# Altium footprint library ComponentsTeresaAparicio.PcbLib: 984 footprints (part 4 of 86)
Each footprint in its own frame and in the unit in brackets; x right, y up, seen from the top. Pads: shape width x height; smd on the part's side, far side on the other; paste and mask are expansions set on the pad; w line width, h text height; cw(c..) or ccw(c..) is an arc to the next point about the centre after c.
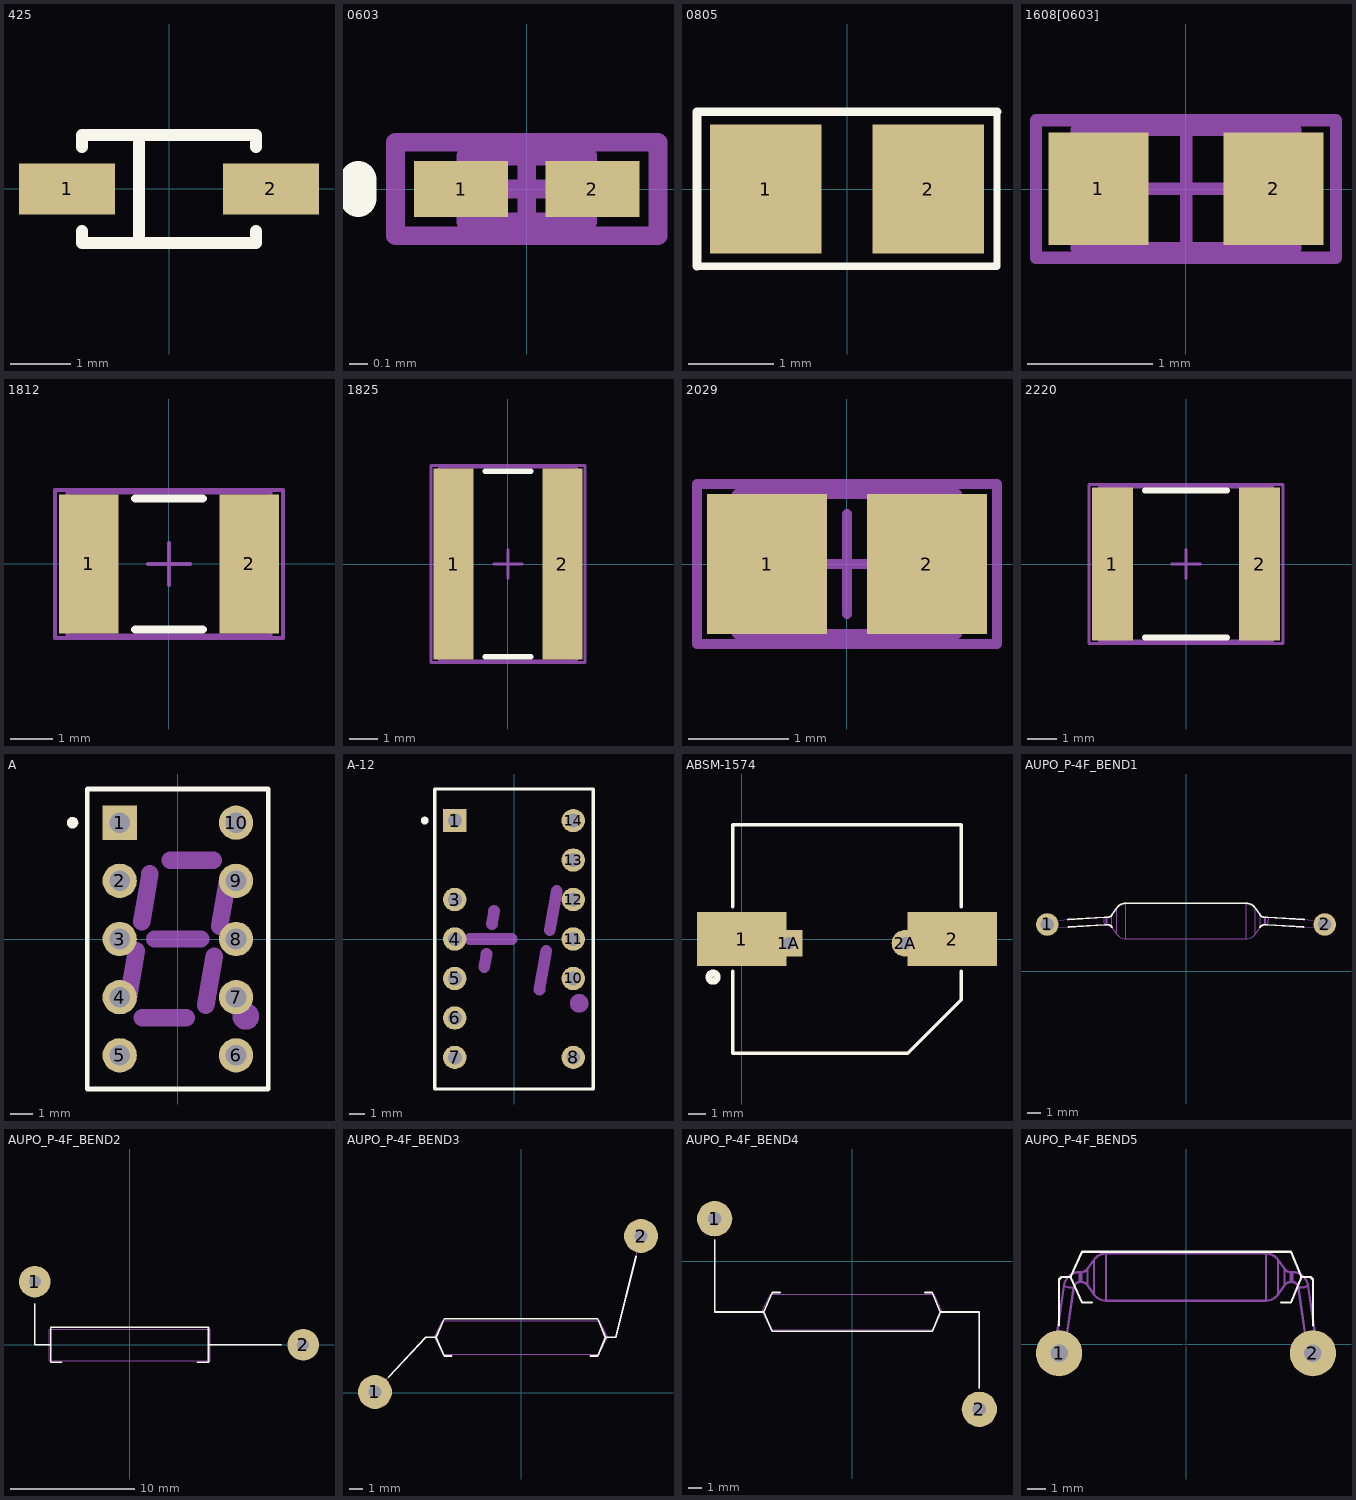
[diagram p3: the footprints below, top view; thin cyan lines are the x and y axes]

## 425 [mm] "SOD-123; 2 Leads; Body 2.7 x 1.6 mm, (LxW)"
height 1.35
pads (2):
  rect 1.6x0.85 smd: 1(-1.7,0) 2(1.7,0)
Top Overlay:
  lines w0.2: -1.45,-0.7 -1.45,-0.9 1.45,-0.9 1.45,-0.7 ; -1.45,0.7 -1.45,0.9 1.45,0.9 1.45,0.7 ; -0.5,-0.9 -0.5,0.9

## 0603 [mm] "Chip Inductor, Body 0.6x0.3mm, IPC High Density"
height 0.55
pads (2):
  rect 0.5x0.3 smd: 1(-0.35,0) 2(0.35,0)
Top Overlay:
  lines w0.2: -0.9,-0.05 -0.9,0.05
Mechanical 13:
  lines w0.1: -0.325,-0.175 0.325,-0.175 0.325,0.175 -0.325,0.175 -0.325,-0.175
Mechanical 15:
  lines w0.1: -0.175,0 0.175,0 ; 0,-0.175 0,0.175 ; -0.7,-0.25 0.7,-0.25 0.7,0.25 -0.7,0.25 -0.7,-0.25
3D body: height 0.55, standoff 0, extent -0.325,-0.175 0.325,0.175

## 0805 [mm] "Chip Capacitor; Body 2.0 x 1.2 mm (LxW typ)"
height 1.3
pads (2):
  rect 1.3x1.5 smd: 1(-0.95,0) 2(0.95,0)
Top Overlay:
  lines w0.086: -1.75,-0.9 1.75,-0.9 1.75,0.9
  lines w0.1: -1.75,-0.9 -1.75,0.9 1.75,0.9

## 1608[0603] [mm] "Chip Capacitor, Body 1.6x0.8mm, IPC High Density"
height 1.3
pads (2):
  rect 0.8x0.9 smd: 1(-0.7,0) 2(0.7,0)
Mechanical 13:
  lines w0.1: -0.875,-0.475 0.875,-0.475 0.875,0.475 -0.875,0.475 -0.875,-0.475
Mechanical 15:
  lines w0.1: -0.475,0 0.475,0 ; 0,-0.475 0,0.475 ; -1.2,-0.55 1.2,-0.55 1.2,0.55 -1.2,0.55 -1.2,-0.55
3D body: height 1.3, standoff 0, extent -0.875,-0.475 0.875,0.475

## 1812 [mm] "Chip Capacitor, Body 4.5x3.2mm, IPC High Density"
height 1.4
pads (2):
  rect 1.4x3.3 smd: 1(-1.9,0) 2(1.9,0)
Top Overlay:
  lines w0.2: -0.8,-1.55 0.8,-1.55 ; -0.8,1.55 0.8,1.55
Mechanical 13:
  lines w0.1: -2.4,-1.7 -2.4,1.7 2.4,1.7 2.4,-1.7 -2.4,-1.7
Mechanical 15:
  lines w0.1: -0.5,0 0.5,0 ; 0,-0.5 0,0.5 ; -2.7,-1.75 -2.7,1.75 2.7,1.75 2.7,-1.75 -2.7,-1.75
3D body: height 1.4, standoff 0, extent -2.4,-1.7 2.4,1.7

## 1825 [mm] "Chip Capacitor, Body 4.5x6.4mm, IPC High Density"
height 1.4
pads (2):
  rect 1.4x6.7 smd: 1(-1.9,0) 2(1.9,0)
Top Overlay:
  lines w0.2: -0.8,-3.25 0.8,-3.25 ; -0.8,3.25 0.8,3.25
Mechanical 13:
  lines w0.1: -2.4,-3.4 -2.4,3.4 2.4,3.4 2.4,-3.4 -2.4,-3.4
Mechanical 15:
  lines w0.1: -0.5,0 0.5,0 ; 0,-0.5 0,0.5 ; -2.7,-3.45 -2.7,3.45 2.7,3.45 2.7,-3.45 -2.7,-3.45
3D body: height 1.4, standoff 0, extent -2.4,-3.4 2.4,3.4

## 2029 [mm] "Chip Inductor, Body 2.0x1.2mm, IPC High Density"
height 0.55
pads (2):
  rect 1.2x1.4 smd: 1(-0.8,0) 2(0.8,0)
Mechanical 13:
  lines w0.1: -1.1,-0.7 1.1,-0.7 1.1,0.7 -1.1,0.7 -1.1,-0.7
Mechanical 15:
  lines w0.1: -0.5,0 0.5,0 ; 0,-0.5 0,0.5 ; -1.5,-0.8 1.5,-0.8 1.5,0.8 -1.5,0.8 -1.5,-0.8
3D body: height 0.55, standoff 0, extent -1.1,-0.7 1.1,0.7

## 2220 [mm] "Chip Capacitor, Body 5.7x5.0mm, IPC High Density"
height 1.4
pads (2):
  rect 1.4x5.2 smd: 1(-2.5,0) 2(2.5,0)
Top Overlay:
  lines w0.2: -1.4,-2.5 1.4,-2.5 ; -1.4,2.5 1.4,2.5
Mechanical 13:
  lines w0.1: -2.95,-2.625 2.95,-2.625 2.95,2.625 -2.95,2.625 -2.95,-2.625
Mechanical 15:
  lines w0.1: -0.5,0 0.5,0 ; 0,-0.5 0,0.5 ; -3.3,-2.7 3.3,-2.7 3.3,2.7 -3.3,2.7 -3.3,-2.7
3D body: height 1.4, standoff 0, extent -2.95,-2.625 2.95,2.625

## A [mm] "LED, 7-Segment Display, 7.62 mm, RHD; 10 Leads; Row Space 5.08 mm; Pitch 2.54 mm"
height 6.34
pads (10):
  rect 1.5x1.5 hole 0.9: 1(-2.54,5.08)
  round 1.5 hole 0.9: 2(-2.54,2.54) 3(-2.54,0) 4(-2.54,-2.54) 5(-2.54,-5.08) 6(2.54,-5.08) 7(2.54,-2.54) 8(2.54,0) 9(2.54,2.54) 10(2.54,5.08)
Top Overlay:
  circle w0.25: c-4.6,5.08 r0.125
  lines w0.2: -3.95,-6.55 3.95,-6.55 3.95,6.55 -3.95,6.55 -3.95,-6.55
Mechanical 1:
  circle w0.86: c2.97,-3.38 r0.15
  lines w0.762: -2.19,-2.69 -1.81,-0.52 ; -1.58,0.76 -1.22,2.84 ; -1.56,-3.43 0.36,-3.43 ; -1.004,0 1.004,0 ; -0.34,3.43 1.55,3.43 ; 1.22,-2.89 1.59,-0.76 ; 1.82,0.56 2.2,2.69
Mechanical 13:
  lines w0.1: -3.95,-6.55 3.95,-6.55 3.95,6.55 -3.95,6.55 -3.95,-6.55
3D body: height 6.34, standoff 0, extent -3.95,-6.55 3.95,6.55

## A-12 [mm] "LED, Universal ±1 Overflow, 7.62 mm, RHD; 14 Leads (2 Absent); Row Space 7.62 mm; Pitch 2.54 mm"
height 6.35
pads (12):
  rect 1.5x1.5 hole 0.9: 1(-3.81,7.62)
  round 1.5 hole 0.9: 3(-3.81,2.54) 4(-3.81,0) 5(-3.81,-2.54) 6(-3.81,-5.08) 7(-3.81,-7.62) 8(3.81,-7.62) 10(3.81,-2.54) 11(3.81,0) 12(3.81,2.54) 13(3.81,5.08) 14(3.81,7.62)
Top Overlay:
  circle w0.25: c-5.75,7.62 r0.125
  lines w0.2: -5.1,-9.65 5.1,-9.65 5.1,9.65 -5.1,9.65 -5.1,-9.65
Mechanical 1:
  circle w0.86: c4.19,-4.139 r0.17
  lines w0.762: -2.83,0 -0.17,0 ; -1.911,-1.799 -1.764,-0.962 ; -1.427,0.961 -1.28,1.8 ; 1.63,-3.262 2.071,-0.764 ; 2.303,0.565 2.747,3.084
Mechanical 13:
  lines w0.1: -5.1,-9.65 -5.1,9.65 5.1,9.65 5.1,-9.65 -5.1,-9.65
3D body: height 6.35, standoff 0, extent -5.1,-9.65 5.1,9.65

## ABSM-1574 [mm] "Magnetic Transducer Buzzer"
pads (4):
  rect 5x3 smd: 1(0,0) 2(11.8,0)
  rect 1.5x1.5 hole 0.7: 1A(2.65,-0.24)
  round 1.5 hole 0.7: 2A(9.15,-0.24)
Top Overlay:
  circle w0.4: c-1.6,-2.134 r0.227
  lines w0.2: -0.5,-1.8 -0.5,-6.4 9.3,-6.4 12.3,-3.4 12.3,-1.8 ; -0.5,1.8 -0.5,6.4 12.3,6.4 12.3,1.8

## AUPO_P-4F_BEND1 [mil] "Aupo P-4F TCO for positioning on IC legs"
height 100
pads (3):
  round 19.68 on Mech14: 0(0,0)
  round 65 / inner round 65 / far side round 90 hole 38: 1(-400,135) 2(400,135)
Top Overlay:
  lines w5: -339.97,149.43 -235.55,155.67 -232.42,155.8 -230.32,155.83 -226.38,155.83 ccw(c-226.38,171.57) -213.48,162.54 -199.33,182.75 cw(c-173.53,164.69) -173.53,196.18 173.53,196.18 cw(c173.53,164.69) 199.33,182.75 213.48,162.54 ccw(c226.38,171.57) 226.38,155.83 230.32,155.83 233.46,155.77 235.55,155.67 340.26,149.42 ; -338.67,127.82 -234.26,134.06 -232.69,134.13 -230.32,134.17 -226.38,134.17 cw(c-226.38,118.43) -213.48,127.46 ; 213.48,127.46 cw(c226.38,118.43) 226.38,134.17 230.32,134.17 231.91,134.15 234.26,134.06 338.97,127.8
Mechanical 13:
  lines w1.97: -381.43,146.96 ccw(c-360.21,137.38) -380.14,125.34 ; 380.14,125.34 ccw(c367.63,134.29) 382.82,136.67 382.89,139.15 382.84,141.46 382.68,143.49 382.42,145.12 382.08,146.27 381.66,146.87 381.43,146.96 ; -235.55,155.67 ccw(c-214.34,146.09) -234.26,134.06 ; -235.55,155.67 -400.65,145.81 ccw(c-400,135) -399.35,124.19 -234.26,134.06 ; -235.55,155.67 -232.42,155.8 -230.32,155.83 ; -234.26,134.06 -232.69,134.13 -230.32,134.17 ; -230.32,134.17 -230.32,155.83 ; -230.32,134.17 -226.38,134.17 ; -230.32,155.83 -226.38,155.83 ; -226.38,134.17 cw(c-226.38,118.43) -213.48,127.46 ; -226.38,134.17 -226.38,155.83 ; -226.38,155.83 ccw(c-226.38,171.57) -213.48,162.54 ; -213.48,127.46 -213.48,162.54 ; -213.48,127.46 -199.33,107.25 ; -213.48,162.54 -199.33,182.75 ; -199.33,107.25 ccw(c-173.53,125.31) -173.53,93.82 ; -199.33,107.25 -199.33,182.75 ; -199.33,182.75 cw(c-173.53,164.69) -173.53,196.18 ; -173.53,93.82 -173.53,196.18 ; -173.53,93.82 173.53,93.82 ; -173.53,196.18 173.53,196.18 ; 173.53,93.82 ccw(c173.53,125.31) 199.33,107.25 ; 173.53,93.82 173.53,196.18 ; 173.53,196.18 cw(c173.53,164.69) 199.33,182.75 ; 199.33,107.25 199.33,182.75 ; 199.33,107.25 213.48,127.46 ; 199.33,182.75 213.48,162.54 ; 213.48,127.46 cw(c226.38,118.43) 226.38,134.17 ; 213.48,127.46 213.48,162.54 ; 213.48,162.54 ccw(c226.38,171.57) 226.38,155.83 ; 226.38,134.17 226.38,155.83 ; 226.38,134.17 230.32,134.17 ; 226.38,155.83 230.32,155.83 ; 230.32,134.17 230.32,155.83 ; 230.32,134.17 231.91,134.15 234.26,134.06 ; 230.32,155.83 233.46,155.77 235.55,155.67 ; 234.26,134.06 ccw(c221.76,143) 236.94,145.39 237.01,147.87 236.96,150.18 236.8,152.21 236.54,153.84 236.19,154.98 235.77,155.59 235.55,155.67 ; 234.26,134.06 399.35,124.19 ccw(c400,135) 400.65,145.81 235.55,155.67
3D body: height 40, standoff 0, extent -444.64,90.1 -355,179.92
3D body: height 104.36, standoff -98, extent -410.74,93.93 410.83,196.09
3D body: height 40, standoff 0, extent 355.36,90.1 445,179.92

## AUPO_P-4F_BEND2 [mil] "Aupo P-4F TCO for positioning on IC legs"
height 100
pads (2):
  round 100 hole 38: 1(-300,200) 2(550,0)
Top Overlay:
  lines w5: -300,130 -300,0 -250,0 ; -215,-55 -250,-55 -250,55 250,55 250,-55 215,-55 ; 250,0 480,0
Mechanical 13:
  lines w3: -255,-50 -255,49.8 255,49.8 255,-50 -255,-50
3D body: height 55, standoff -95, extent -310,190.02 -290.08,209.98
3D body: height 65, standoff 45.08, extent -309.98,-0.02 -290.02,199.98
3D body: height 65, standoff 45.08, extent -299.5,-9.96 -254.5,10
3D body: height 65, standoff 45.08, extent 250,-9.96 550,10
3D body: height 104.61, standoff 5, extent -255,-50 255,49.8
3D body: height 55, standoff -95, extent 540,-9.98 559.92,9.99
3D body: height 65, standoff 45, extent 540,-9.98 559.9,9.94
3D body: height 65, standoff 45, extent -310,190.02 -290.1,209.94
3D body: height 65, standoff 45, extent -310,-10 -290.1,9.91

## AUPO_P-4F_BEND3 [mil] "Aupo P-4F TCO for positioning on IC legs"
height 100
pads (2):
  round 100 hole 38: 1(-431,3) 2(354,463)
Top Overlay:
  lines w5: -389.97,47.04 -281,164 -251,164 ; -205,109 -226.33,109 -251,164 ; 205,109 226.41,109 249,164 ; 338.95,403.01 279,164 249,164 ; -251,164 -226.38,219 226.38,219 249,164
Mechanical 13:
  lines w3: -431,3 -280.63,164.37 -256,164.37 -231.3,213.8 231.3,213.8 254,164.37 278.63,164.37 354,463 ; -256,163.9 -231.3,114 231.3,114 254,163.9
3D body: height 105.02, standoff -94.88, extent -440.35,-6.96 364.65,473.01

## AUPO_P-4F_BEND4 [mil] "Aupo P-4F TCO for positioning on IC legs"
height 100
pads (2):
  round 100 hole 38: 1(-390,120) 2(360,-420)
Top Overlay:
  lines w5: -390,60 -390,-144 -251,-144 ; -226.38,-199 226.38,-199 249,-144 ; -226.38,-89 -251,-144 ; -226.33,-199 -251,-144 ; -226.33,-89 -205,-89 ; 205,-89 226.41,-89 249,-144 ; 360,-360 360,-144 249,-144
Mechanical 13:
  lines w3: -390,60 -390,-144 -256,-144 ; -256,-144.1 -231.3,-194 231.3,-194 254,-144.1 ; -256,-143.63 -231.3,-94.2 231.3,-94.2 254,-143.63 ; 254,-144 360,-144 360,-360
3D body: height 105.02, standoff -94.88, extent -399.95,-430.6 369.97,129.36

## AUPO_P-4F_BEND5 [mil] "Aupo P-4F TCO for positioning on IC legs"
height 100
pads (3):
  round 19.68 on Mech14: 0(0,0)
  round 100 hole 38: 1(-275,-20) 2(275,-20)
Top Overlay:
  lines w5: -275,40 -275,140 -270,145 -250,145 ; -204,90 -225.33,90 -250,145 ; 206,90 227.41,90 250,145 ; 275,40 275,140 270,145 250,145 ; -250,145 -225.38,200 227.38,200 250,145
Mechanical 13:
  lines w5: -282.92,0.59 ccw(c-269.19,19.56) -261.5,-2.55 ; 261.5,-2.55 ccw(c268.97,22.97) 282.85,0.28 282.92,0.59 ; -264.41,126.68 ccw(c-250.67,145.69) -242.98,123.53 ; -264.41,126.68 cw(c-230.49,121.52) -230.32,155.83 ; -264.41,126.68 -285.71,-18.43 ccw(c-275,-20) -264.29,-21.57 -242.98,123.54 ; -242.98,123.54 cw(c-230.48,121.51) -230.32,134.17 ; -230.32,134.17 -230.32,155.83 ; -230.32,134.17 -226.38,134.17 ; -230.32,155.83 -226.38,155.83 ; -226.38,134.17 cw(c-226.38,118.43) -213.48,127.46 ; -226.38,134.17 -226.38,155.83 ; -226.38,155.83 ccw(c-226.38,171.57) -213.48,162.54 ; -213.48,127.46 -213.48,162.54 ; -213.48,127.46 -199.33,107.25 ; -213.48,162.54 -199.33,182.75 ; -199.33,107.25 ccw(c-173.53,125.31) -173.53,93.82 ; -199.33,107.25 -199.33,182.75 ; -199.33,182.75 cw(c-173.53,164.69) -173.53,196.18 ; -173.53,93.82 -173.53,196.18 ; -173.53,93.82 173.53,93.82 ; -173.53,196.18 173.53,196.18 ; 173.53,93.82 ccw(c173.53,125.31) 199.33,107.25 ; 173.53,93.82 173.53,196.18 ; 173.53,196.18 cw(c173.53,164.69) 199.33,182.75 ; 199.33,107.25 199.33,182.75 ; 199.33,107.25 213.48,127.46 ; 199.33,182.75 213.48,162.54 ; 213.48,127.46 cw(c226.38,118.43) 226.38,134.17 ; 213.48,127.46 213.48,162.54 ; 213.48,162.54 ccw(c226.38,171.57) 226.38,155.83 ; 226.38,134.17 226.38,155.83 ; 226.38,134.17 230.32,134.17 ; 226.38,155.83 230.32,155.83 ; 230.32,134.17 cw(c230.48,121.51) 242.98,123.54 ; 230.32,134.17 230.32,155.83 ; 230.32,155.83 cw(c230.49,121.51) 264.41,126.68 ; 242.98,123.54 ccw(c250.45,149.1) 264.34,126.38 264.41,126.68 ; 242.98,123.54 264.29,-21.57 ccw(c275,-20) 285.83,-20 285.71,-18.43 264.41,126.68
3D body: height 102.36, standoff -100, extent -285.73,-30.8 285.83,196.09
